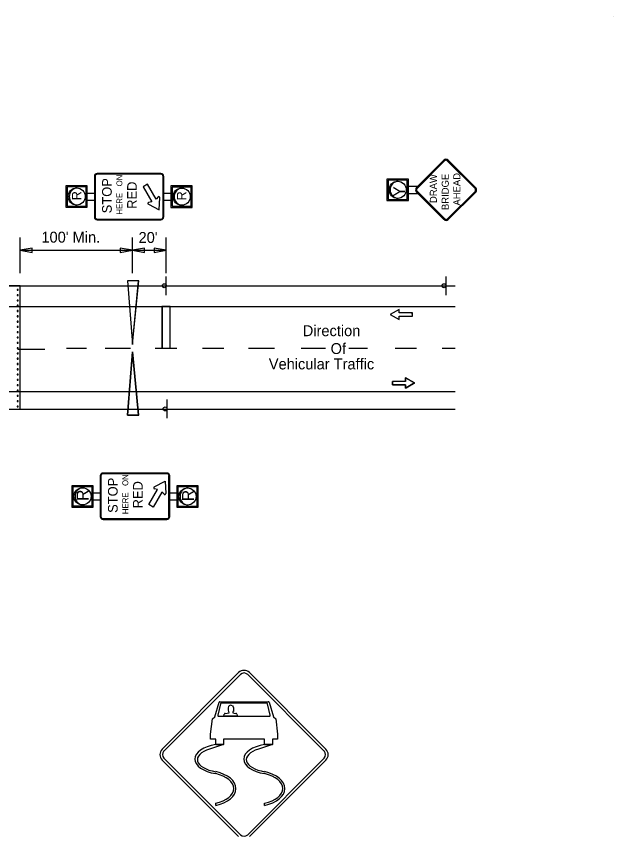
# Model space of a CAD drawing. Extents: x 10000 to 10825, y 10000 to 10530.
# Drawn here: x 10633.4 to 10825, y 10267.1 to 10530 of the extents above; entities that cross this region are included whole.
import ezdxf

# ---------------------------------------------------------------- set-up
doc = ezdxf.new("R2010")
doc.units = 0
for name, color, linetype in [('Default', 7, 'Continuous'), ('Dimension', 7, 'Continuous'), ('TextStructures', 7, 'Continuous')]:
    doc.layers.add(name, color=color, linetype=linetype)

msp = doc.modelspace()

# ---------------------------------------------------------------- linework, layer by layer
at = {"layer": 'Default'}
for p, q in [((10824.98, 10529.98), (10824.98, 10529.98)), ((10770.5, 10483.91), (10761.68, 10475.09)), ((10770.73, 10483.68), (10761.91, 10474.86)), ((10780.51, 10474.79), (10771.63, 10483.68)), ((10780.74, 10475.02), (10771.86, 10483.91)), ((10679.75, 10479.65), (10659.32, 10479.65)), ((10679.75, 10479.42), (10659.32, 10479.42)), ((10658.39, 10478.72), (10658.39, 10465.72)), ((10658.62, 10478.72), (10658.62, 10465.72)), ((10675.41, 10476.19), (10674, 10475.38)), ((10678.19, 10471.38), (10675.41, 10476.19)), ((10680.45, 10465.72), (10680.45, 10478.72)), ((10680.68, 10465.72), (10680.68, 10478.72)), ((10759.12, 10477.83), (10752.26, 10477.83)), ((10752.26, 10477.83), (10752.26, 10470.98)), ((10758.77, 10477.49), (10752.61, 10477.49)), ((10752.61, 10477.49), (10752.61, 10471.32)), ((10758.77, 10471.32), (10758.77, 10477.49)), ((10759.12, 10470.98), (10759.12, 10477.83)), ((10656.13, 10475.68), (10649.28, 10475.68)), ((10649.28, 10475.68), (10649.28, 10468.83)), ((10655.79, 10475.34), (10649.62, 10475.34)), ((10649.62, 10475.34), (10649.62, 10469.17)), ((10655.79, 10469.17), (10655.79, 10475.34)), ((10656.13, 10468.83), (10656.13, 10475.68)), ((10674, 10475.38), (10676.78, 10470.57)), ((10689.81, 10475.63), (10682.96, 10475.63)), ((10682.96, 10475.63), (10682.96, 10468.78)), ((10689.47, 10475.29), (10683.3, 10475.29)), ((10683.3, 10475.29), (10683.3, 10469.12)), ((10689.47, 10469.12), (10689.47, 10475.29)), ((10689.81, 10468.78), (10689.81, 10475.63)), ((10759.14, 10475.54), (10762.13, 10475.54)), ((10770.56, 10464.85), (10761.68, 10473.74)), ((10770.79, 10465.08), (10761.91, 10473.96)), ((10780.51, 10473.89), (10771.69, 10465.08)), ((10780.74, 10473.67), (10771.92, 10464.85)), ((10656.12, 10473.35), (10658.39, 10473.35)), ((10656.12, 10471.09), (10658.39, 10471.09)), ((10678.88, 10472.13), (10678.19, 10471.38)), ((10679.23, 10467.94), (10679.41, 10471.9)), ((10680.68, 10473.35), (10682.95, 10473.35)), ((10680.68, 10471.09), (10682.95, 10471.09)), ((10752.26, 10470.98), (10759.12, 10470.98)), ((10752.61, 10471.32), (10758.77, 10471.32)), ((10759.14, 10473.27), (10762.14, 10473.27)), ((10767.7, 10472.81), (10767.7, 10472.81)), ((10649.28, 10468.83), (10656.13, 10468.83)), ((10649.62, 10469.17), (10655.79, 10469.17)), ((10675.71, 10469.77), (10679.23, 10467.94)), ((10676.78, 10470.57), (10675.78, 10470.34)), ((10682.96, 10468.78), (10689.81, 10468.78)), ((10683.3, 10469.12), (10689.47, 10469.12)), ((10659.32, 10465.02), (10679.75, 10465.02)), ((10659.32, 10464.79), (10679.75, 10464.79)), ((10634.55, 10447.64), (10634.55, 10459.12)), ((10670.61, 10447.64), (10670.61, 10459.12)), ((10681.47, 10447.64), (10681.47, 10459.12)), ((10634.55, 10455.02), (10670.61, 10455.02)), ((10670.61, 10455.02), (10681.47, 10455.02)), ((10672.58, 10445.18), (10668.97, 10445.18)), ((10668.97, 10445.18), (10670.65, 10424.85)), ((10672.58, 10445.18), (10669.02, 10445.18)), ((10670.65, 10424.85), (10672.58, 10445.18)), ((10670.66, 10424.91), (10672.58, 10445.18)), ((10681.47, 10440.68), (10681.47, 10446.63)), ((10771.21, 10440.68), (10771.21, 10446.62)), ((10429.35, 10443.61), (10774.15, 10443.61)), ((10634.55, 10443.61), (10566.84, 10443.61)), ((10634.55, 10404.14), (10634.55, 10443.61)), ((10634.55, 10443.61), (10669.1, 10443.61)), ((10429.35, 10437.05), (10774.15, 10437.05)), ((10756.15, 10436.08), (10753.24, 10434.45)), ((10753.24, 10434.45), (10756.14, 10432.81)), ((10756.15, 10434.99), (10756.15, 10436.08)), ((10756.15, 10434.99), (10756.15, 10435.65)), ((10760.41, 10434.99), (10756.15, 10434.99)), ((10759.49, 10434.99), (10756.15, 10434.99)), ((10760.41, 10433.9), (10760.41, 10434.99)), ((10756.14, 10432.81), (10756.14, 10433.9)), ((10756.14, 10433.9), (10760.41, 10433.9)), ((10756.14, 10432.81), (10756.14, 10433.9)), ((10756.14, 10433.9), (10756.16, 10433.9)), ((10756.14, 10432.82), (10756.14, 10432.81)), ((10649.46, 10423.67), (10655.91, 10423.67)), ((10661.89, 10423.67), (10669.95, 10423.67)), ((10677.85, 10423.67), (10684.85, 10423.67)), ((10680.12, 10423.67), (10682.71, 10423.67)), ((10693.09, 10423.67), (10699.95, 10423.67)), ((10707.87, 10423.67), (10716.13, 10423.67)), ((10724.78, 10423.67), (10732.5, 10423.67)), ((10740.04, 10423.67), (10745.97, 10423.67)), ((10754.89, 10423.67), (10761.77, 10423.67)), ((10770.01, 10423.67), (10774.15, 10423.67)), ((10633.83, 10423.37), (10642.48, 10423.37)), ((10668.97, 10402.17), (10670.65, 10422.5)), ((10670.65, 10422.5), (10672.58, 10402.17)), ((10672.58, 10402.17), (10670.65, 10422.5)), ((10758.25, 10414.1), (10758.24, 10413.01)), ((10758.25, 10414.1), (10758.24, 10413.01)), ((10761.15, 10412.46), (10758.25, 10414.1)), ((10761.11, 10412.49), (10758.25, 10414.1)), ((10758.24, 10413.01), (10753.99, 10413.01)), ((10753.99, 10413.01), (10753.99, 10411.92)), ((10758.24, 10413.01), (10753.99, 10413.01)), ((10753.99, 10411.92), (10758.24, 10411.92)), ((10758.24, 10410.84), (10761.15, 10412.46)), ((10758.24, 10411.92), (10758.24, 10410.84)), ((10758.24, 10410.84), (10758.4, 10410.93)), ((10429.35, 10409.73), (10774.15, 10409.73)), ((10681.74, 10401.2), (10681.74, 10407.15)), ((10429.35, 10404.14), (10774.15, 10404.14)), ((10566.84, 10404.14), (10634.55, 10404.14)), ((10672.58, 10402.17), (10668.97, 10402.17)), ((10669.01, 10402.17), (10672.58, 10402.17)), ((10660.27, 10382.7), (10660.27, 10369.7)), ((10660.5, 10382.7), (10660.5, 10369.7)), ((10681.64, 10383.63), (10661.2, 10383.63)), ((10681.64, 10383.4), (10661.2, 10383.4)), ((10682.33, 10369.7), (10682.33, 10382.7)), ((10682.56, 10369.7), (10682.56, 10382.7)), ((10658, 10379.57), (10651.15, 10379.57)), ((10651.15, 10379.57), (10651.15, 10372.72)), ((10657.66, 10379.23), (10651.49, 10379.23)), ((10651.49, 10379.23), (10651.49, 10373.06)), ((10657.66, 10373.06), (10657.66, 10379.23)), ((10658, 10372.72), (10658, 10379.57)), ((10677.6, 10379.15), (10681.12, 10380.98)), ((10681.12, 10380.98), (10681.3, 10377.02)), ((10691.69, 10379.53), (10684.84, 10379.53)), ((10684.84, 10379.53), (10684.84, 10372.68)), ((10691.35, 10379.19), (10685.18, 10379.19)), ((10685.18, 10379.19), (10685.18, 10373.02)), ((10691.35, 10373.02), (10691.35, 10379.19)), ((10691.69, 10372.68), (10691.69, 10379.53)), ((10658.01, 10377.33), (10660.27, 10377.33)), ((10675.88, 10373.54), (10678.66, 10378.36)), ((10680.07, 10377.54), (10677.29, 10372.73)), ((10678.66, 10378.36), (10677.67, 10378.59)), ((10680.77, 10376.8), (10680.07, 10377.54)), ((10682.56, 10377.33), (10684.83, 10377.33)), ((10658.01, 10375.07), (10660.27, 10375.07)), ((10682.56, 10375.07), (10684.83, 10375.07)), ((10651.15, 10372.72), (10658, 10372.72)), ((10651.49, 10373.06), (10657.66, 10373.06)), ((10677.29, 10372.73), (10675.88, 10373.54)), ((10684.84, 10372.68), (10691.69, 10372.68)), ((10685.18, 10373.02), (10691.35, 10373.02)), ((10661.2, 10369), (10681.64, 10369)), ((10661.2, 10368.77), (10681.64, 10368.77)), ((10704.66, 10319.64), (10680.14, 10295.12)), ((10705.25, 10319.06), (10680.73, 10294.53)), ((10732.1, 10294.53), (10707.58, 10319.06)), ((10732.69, 10295.12), (10708.17, 10319.64)), ((10697, 10305.52), (10698.4, 10310.14)), ((10698.88, 10309.65), (10698.01, 10305.98)), ((10698.64, 10310.31), (10714.19, 10310.31)), ((10713.7, 10309.84), (10699.13, 10309.84)), ((10701.42, 10308.22), (10701.5, 10308.86)), ((10701.42, 10307.59), (10701.42, 10308.22)), ((10701.5, 10308.86), (10701.66, 10309.02)), ((10702.69, 10309.02), (10702.93, 10308.7)), ((10702.93, 10308.7), (10703, 10308.38)), ((10703, 10308.38), (10703.08, 10307.91)), ((10714.82, 10305.98), (10713.94, 10309.65)), ((10714.43, 10310.14), (10715.83, 10305.52)), ((10696.27, 10304.79), (10697, 10305.52)), ((10698.25, 10305.67), (10714.58, 10305.67)), ((10699.91, 10305.69), (10700.07, 10306.32)), ((10704.28, 10305.67), (10699.95, 10305.67)), ((10700.39, 10306.56), (10701.66, 10306.72)), ((10701.66, 10306.72), (10701.42, 10307.59)), ((10702.85, 10307.19), (10702.77, 10307.04)), ((10702.77, 10307.04), (10702.85, 10306.72)), ((10703, 10307.19), (10702.85, 10307.19)), ((10702.85, 10306.72), (10703.72, 10306.56)), ((10703.08, 10307.91), (10703, 10307.19)), ((10704.11, 10306.32), (10704.27, 10305.69)), ((10715.83, 10305.52), (10716.56, 10304.79)), ((10695.68, 10299.94), (10696.27, 10304.79)), ((10716.56, 10304.79), (10717.15, 10299.94)), ((10695.68, 10298.29), (10695.68, 10299.94)), ((10697.33, 10298.29), (10695.68, 10298.29)), ((10697.33, 10296.64), (10697.33, 10298.29)), ((10713.02, 10298.29), (10699.81, 10298.29)), ((10699.81, 10298.29), (10699.81, 10296.64)), ((10713.02, 10296.64), (10713.02, 10298.29)), ((10717.15, 10298.29), (10715.5, 10298.29)), ((10715.5, 10298.29), (10715.5, 10296.64)), ((10717.15, 10299.94), (10717.15, 10298.29)), ((10699.81, 10296.64), (10695.32, 10295.16)), ((10697.33, 10296.64), (10699.81, 10296.64)), ((10699.81, 10296.64), (10697.33, 10296.64)), ((10715.5, 10296.64), (10711, 10295.16)), ((10713.02, 10296.64), (10715.5, 10296.64)), ((10715.5, 10296.64), (10713.02, 10296.64)), ((10680.73, 10292.2), (10705.25, 10267.68)), ((10707.58, 10267.68), (10732.1, 10292.2)), ((10680.14, 10291.62), (10704.66, 10267.1)), ((10708.17, 10267.1), (10732.69, 10291.62)), ((10697.33, 10277.07), (10697.33, 10277.77)), ((10713.02, 10277.07), (10713.02, 10277.77))]:
    msp.add_line(p, q, dxfattribs=at)
for points in [[(10672.61, 10445.2), (10669.02, 10445.2), (10670.66, 10424.91)], [(10680.09, 10437.05), (10680.09, 10423.67), (10682.72, 10423.67), (10682.72, 10437.05)], [(10682.68, 10437.05), (10680.12, 10437.05), (10680.12, 10423.67), (10682.71, 10423.67)], [(10756.14, 10436.07), (10753.25, 10434.46), (10756.14, 10432.82), (10756.16, 10433.9), (10760.41, 10433.91), (10760.4, 10434.99), (10756.16, 10434.99)], [(10669.01, 10402.17), (10672.62, 10402.12), (10670.65, 10422.5)], [(10753.99, 10413.01), (10758.24, 10413.03), (10758.25, 10414.1), (10761.11, 10412.49), (10758.38, 10410.92), (10758.23, 10410.84), (10758.23, 10411.92), (10753.99, 10411.92)]]:
    msp.add_lwpolyline(points, close=True, dxfattribs=at)
for points in [[(10669.02, 10445.18), (10670.66, 10424.91)], [(10633.9, 10442.22), (10633.9, 10442.48), (10633.64, 10442.48), (10633.64, 10442.22), (10633.9, 10442.22)], [(10633.9, 10442.22), (10633.9, 10442.48), (10633.64, 10442.48), (10633.64, 10442.22), (10633.9, 10442.22)], [(10633.9, 10440.52), (10633.9, 10440.78), (10633.64, 10440.78), (10633.64, 10440.52), (10633.9, 10440.52)], [(10633.9, 10440.52), (10633.9, 10440.78), (10633.64, 10440.78), (10633.64, 10440.52), (10633.9, 10440.52)], [(10633.9, 10438.82), (10633.9, 10439.08), (10633.64, 10439.08), (10633.64, 10438.82), (10633.9, 10438.82)], [(10633.9, 10438.82), (10633.9, 10439.08), (10633.64, 10439.08), (10633.64, 10438.82), (10633.9, 10438.82)], [(10633.9, 10437.13), (10633.9, 10437.38), (10633.64, 10437.38), (10633.64, 10437.13), (10633.9, 10437.13)], [(10633.9, 10437.13), (10633.9, 10437.38), (10633.64, 10437.38), (10633.64, 10437.13), (10633.9, 10437.13)], [(10680.09, 10437.02), (10682.72, 10437.02)], [(10682.68, 10437.02), (10680.12, 10437.02)], [(10680.12, 10437.02), (10680.12, 10423.67)], [(10682.71, 10423.67), (10682.68, 10437.02)], [(10633.9, 10435.43), (10633.9, 10435.68), (10633.64, 10435.68), (10633.64, 10435.43), (10633.9, 10435.43)], [(10633.9, 10435.43), (10633.9, 10435.68), (10633.64, 10435.68), (10633.64, 10435.43), (10633.9, 10435.43)], [(10756.15, 10435.65), (10756.14, 10436.07), (10753.25, 10434.46), (10756.14, 10432.82)], [(10756.16, 10433.9), (10760.41, 10433.91), (10760.4, 10434.99), (10759.49, 10434.99)], [(10633.9, 10433.73), (10633.9, 10433.98), (10633.64, 10433.98), (10633.64, 10433.73), (10633.9, 10433.73)], [(10633.9, 10433.73), (10633.9, 10433.98), (10633.64, 10433.98), (10633.64, 10433.73), (10633.9, 10433.73)], [(10633.9, 10432.03), (10633.9, 10432.29), (10633.64, 10432.29), (10633.64, 10432.03), (10633.9, 10432.03)], [(10633.9, 10432.03), (10633.9, 10432.29), (10633.64, 10432.29), (10633.64, 10432.03), (10633.9, 10432.03)], [(10633.9, 10430.33), (10633.9, 10430.59), (10633.64, 10430.59), (10633.64, 10430.33), (10633.9, 10430.33)], [(10633.9, 10430.33), (10633.9, 10430.59), (10633.64, 10430.59), (10633.64, 10430.33), (10633.9, 10430.33)], [(10633.9, 10428.63), (10633.9, 10428.89), (10633.64, 10428.89), (10633.64, 10428.63), (10633.9, 10428.63)], [(10633.9, 10428.63), (10633.9, 10428.89), (10633.64, 10428.89), (10633.64, 10428.63), (10633.9, 10428.63)], [(10633.9, 10426.93), (10633.9, 10427.19), (10633.64, 10427.19), (10633.64, 10426.93), (10633.9, 10426.93)], [(10633.9, 10426.93), (10633.9, 10427.19), (10633.64, 10427.19), (10633.64, 10426.93), (10633.9, 10426.93)], [(10633.9, 10425.24), (10633.9, 10425.49), (10633.64, 10425.49), (10633.64, 10425.24), (10633.9, 10425.24)], [(10633.9, 10425.24), (10633.9, 10425.49), (10633.64, 10425.49), (10633.64, 10425.24), (10633.9, 10425.24)], [(10633.9, 10423.54), (10633.9, 10423.79), (10633.64, 10423.79), (10633.64, 10423.54), (10633.9, 10423.54)], [(10633.9, 10423.54), (10633.9, 10423.79), (10633.64, 10423.79), (10633.64, 10423.54), (10633.9, 10423.54)], [(10633.9, 10421.84), (10633.9, 10422.1), (10633.64, 10422.09), (10633.64, 10421.84), (10633.9, 10421.84)], [(10633.9, 10421.84), (10633.9, 10422.1), (10633.64, 10422.09), (10633.64, 10421.84), (10633.9, 10421.84)], [(10670.65, 10422.5), (10669.01, 10402.17)], [(10633.9, 10420.14), (10633.9, 10420.4), (10633.64, 10420.4), (10633.64, 10420.14), (10633.9, 10420.14)], [(10633.9, 10420.14), (10633.9, 10420.4), (10633.64, 10420.4), (10633.64, 10420.14), (10633.9, 10420.14)], [(10633.9, 10418.44), (10633.9, 10418.7), (10633.64, 10418.7), (10633.64, 10418.44), (10633.9, 10418.44)], [(10633.9, 10418.44), (10633.9, 10418.7), (10633.64, 10418.7), (10633.64, 10418.44), (10633.9, 10418.44)], [(10633.9, 10416.74), (10633.9, 10417), (10633.64, 10417), (10633.64, 10416.74), (10633.9, 10416.74)], [(10633.9, 10416.74), (10633.9, 10417), (10633.64, 10417), (10633.64, 10416.74), (10633.9, 10416.74)], [(10633.9, 10415.05), (10633.9, 10415.3), (10633.64, 10415.3), (10633.64, 10415.05), (10633.9, 10415.05)], [(10633.9, 10415.05), (10633.9, 10415.3), (10633.64, 10415.3), (10633.64, 10415.05), (10633.9, 10415.05)], [(10633.9, 10413.35), (10633.9, 10413.6), (10633.64, 10413.6), (10633.64, 10413.35), (10633.9, 10413.35)], [(10633.9, 10413.35), (10633.9, 10413.6), (10633.64, 10413.6), (10633.64, 10413.35), (10633.9, 10413.35)], [(10633.9, 10411.65), (10633.9, 10411.9), (10633.64, 10411.9), (10633.64, 10411.65), (10633.9, 10411.65)], [(10633.9, 10411.65), (10633.9, 10411.9), (10633.64, 10411.9), (10633.64, 10411.65), (10633.9, 10411.65)], [(10753.99, 10413.01), (10753.99, 10411.92), (10758.23, 10411.92)], [(10758.23, 10411.92), (10758.23, 10410.84)], [(10758.4, 10410.93), (10761.11, 10412.49)], [(10633.9, 10409.95), (10633.9, 10410.21), (10633.64, 10410.2), (10633.64, 10409.95), (10633.9, 10409.95)], [(10633.9, 10409.95), (10633.9, 10410.21), (10633.64, 10410.2), (10633.64, 10409.95), (10633.9, 10409.95)], [(10633.9, 10408.25), (10633.9, 10408.51), (10633.64, 10408.51), (10633.64, 10408.25), (10633.9, 10408.25)], [(10633.9, 10408.25), (10633.9, 10408.51), (10633.64, 10408.51), (10633.64, 10408.25), (10633.9, 10408.25)], [(10633.9, 10406.55), (10633.9, 10406.81), (10633.64, 10406.81), (10633.64, 10406.55), (10633.9, 10406.55)], [(10633.9, 10406.55), (10633.9, 10406.81), (10633.64, 10406.81), (10633.64, 10406.55), (10633.9, 10406.55)], [(10633.9, 10404.85), (10633.9, 10405.11), (10633.64, 10405.11), (10633.64, 10404.85), (10633.9, 10404.85)], [(10633.9, 10404.85), (10633.9, 10405.11), (10633.64, 10405.11), (10633.64, 10404.85), (10633.9, 10404.85)]]:
    msp.add_lwpolyline(points, dxfattribs=at)
for centre, radius in [((10755.69, 10474.41), 2.74), ((10652.71, 10472.25), 2.74), ((10686.39, 10472.21), 2.74), ((10680.83, 10443.65), 0.637), ((10770.57, 10443.65), 0.637), ((10681.1, 10404.18), 0.637), ((10654.58, 10376.15), 2.74), ((10688.27, 10376.11), 2.74)]:
    msp.add_circle(centre, radius, dxfattribs=at)
for centre, radius, start, end in [((10771.18, 10483.23), 0.958, 44.9848, 134.9852), ((10771.18, 10483.23), 0.635, 44.9848, 134.9852), ((10659.32, 10478.72), 0.929, 90, 180), ((10659.32, 10478.72), 0.697, 90, 180), ((10679.75, 10478.72), 0.929, 360, 90), ((10679.75, 10478.72), 0.697, 360, 90), ((10756.03, 10474.41), 2.74, 93.5833, 266.4167), ((10653.05, 10472.25), 2.74, 93.5833, 266.4167), ((10686.73, 10472.21), 2.74, 93.5833, 266.4167), ((10762.36, 10474.41), 0.958, 134.9852, 224.9843), ((10762.36, 10474.41), 0.635, 134.9852, 224.9843), ((10780.06, 10474.34), 0.635, 314.9857, 44.9846), ((10780.06, 10474.34), 0.958, 314.9857, 44.9846), ((10679.11, 10471.92), 0.305, 357.4033, 136.9437), ((10675.85, 10470.04), 0.305, 103.0563, 242.5967), ((10659.32, 10465.72), 0.929, 180, 270), ((10659.32, 10465.72), 0.697, 180, 270), ((10679.75, 10465.72), 0.929, 270, 360), ((10679.75, 10465.72), 0.697, 270, 360), ((10771.24, 10465.53), 0.958, 224.9847, 314.9857), ((10771.24, 10465.53), 0.635, 224.9847, 314.9857), ((10661.2, 10382.7), 0.929, 90, 180), ((10661.2, 10382.7), 0.697, 90, 180), ((10681.64, 10382.7), 0.929, 360, 90), ((10681.64, 10382.7), 0.697, 360, 90), ((10677.74, 10378.88), 0.305, 117.4033, 256.9437), ((10654.92, 10376.15), 2.74, 93.5833, 266.4167), ((10680.99, 10377), 0.305, 223.0563, 2.5967), ((10688.61, 10376.11), 2.74, 93.5833, 266.4167), ((10661.2, 10369.7), 0.929, 180, 270), ((10661.2, 10369.7), 0.697, 180, 270), ((10681.64, 10369.7), 0.929, 270, 360), ((10681.64, 10369.7), 0.697, 270, 360), ((10706.41, 10317.89), 2.48, 45, 135), ((10706.41, 10317.89), 1.65, 45, 135), ((10698.64, 10310.07), 0.248, 90, 163.133), ((10699.13, 10309.6), 0.248, 90, 166.6434), ((10702.17, 10308.08), 1.1, 61.5674, 118.4326), ((10713.7, 10309.6), 0.248, 13.3566, 90), ((10714.19, 10310.07), 0.248, 16.8669, 90), ((10698.25, 10305.92), 0.248, 166.6434, 270), ((10700.39, 10306.28), 0.303, 96.2729, 166.6932), ((10703.71, 10306.21), 0.392, 16.03, 82.8338), ((10714.58, 10305.92), 0.248, 270, 13.3566), ((10681.89, 10293.37), 2.48, 135, 225), ((10730.93, 10293.37), 2.48, 315, 45), ((10681.89, 10293.37), 1.65, 135, 225), ((10730.93, 10293.37), 1.65, 315, 45), ((10706.41, 10268.85), 1.65, 225, 315)]:
    msp.add_arc(centre, radius, start, end, dxfattribs=at)
for centre, major_axis, ratio, start_param, end_param in [((10700.56, 10291.95), (9.91, 0), 0.5, 1.902923, 4.380262), ((10700.51, 10291.77), (9.08, 0), 0.454545, 2.180257, 4.354407), ((10716.25, 10291.95), (9.91, 0), 0.5, 1.902923, 4.380262), ((10716.2, 10291.77), (9.08, 0), 0.454545, 2.180257, 4.354407), ((10693.88, 10282.49), (9.91, 0), 0.583333, 5.068422, 7.497948), ((10693.88, 10282.52), (9.25, 0), 0.553572, 5.095121, 7.47125), ((10709.57, 10282.49), (9.91, 0), 0.583333, 5.068422, 7.497948), ((10709.57, 10282.52), (9.25, 0), 0.553572, 5.095121, 7.47125)]:
    msp.add_ellipse(centre, major_axis=major_axis, ratio=ratio, start_param=start_param, end_param=end_param, dxfattribs=at)
at = {"layer": 'Dimension'}
for points in [[(10634.55, 10455.02), (10638.46, 10454.36), (10638.46, 10455.68)], [(10670.61, 10455.02), (10666.71, 10455.68), (10666.71, 10454.36)], [(10670.61, 10455.02), (10674.52, 10454.36), (10674.52, 10455.68)], [(10681.47, 10455.02), (10677.56, 10455.68), (10677.56, 10454.36)]]:
    msp.add_lwpolyline(points, close=True, dxfattribs=at)

# ---------------------------------------------------------------- texts
at = {"layer": 'Default'}
for s, height, p in [('HERE   ON', 1.873, (10667.36, 10466.46)), ('DRAW', 2.265, (10768.27, 10470.17)), ('BRIDGE', 2.265, (10772.09, 10467.92)), ('AHEAD', 2.265, (10775.79, 10469.36)), ('STOP', 3.098, (10663.97, 10466.87)), ('RED', 3.098, (10672, 10468.3)), ('STOP', 3.098, (10665.86, 10370.85)), ('HERE   ON', 1.873, (10669.25, 10370.44)), ('RED', 3.098, (10673.88, 10372.28))]:
    msp.add_text(s, height=height, rotation=90, dxfattribs=at).set_placement(p)
at = {"layer": 'TextStructures'}
for s, height, rotation, p in [('R', 3.08, 90, (10654.25, 10471.02)), ('R', 3.08, 90, (10687.93, 10470.97)), ('Y', 3.78, 90, (10758.05, 10472.18)), ("100' Min.", 3.5, 0.0007, (10641.41, 10457.48)), ("20'", 3.5, 0.0007, (10672.57, 10457.38)), ('R', 3.78, 90, (10656.52, 10374.69)), ('R', 3.78, 90, (10690.32, 10374.59))]:
    msp.add_text(s, height=height, rotation=rotation, dxfattribs=at).set_placement(p)
for s, p in [('Direction', (10725.25, 10427.49)), ('Of', (10734.19, 10421.77)), ('Vehicular Traffic', (10714.36, 10416.84))]:
    msp.add_text(s, height=3.5, dxfattribs=at).set_placement(p)

doc.saveas('drawing.dxf')
